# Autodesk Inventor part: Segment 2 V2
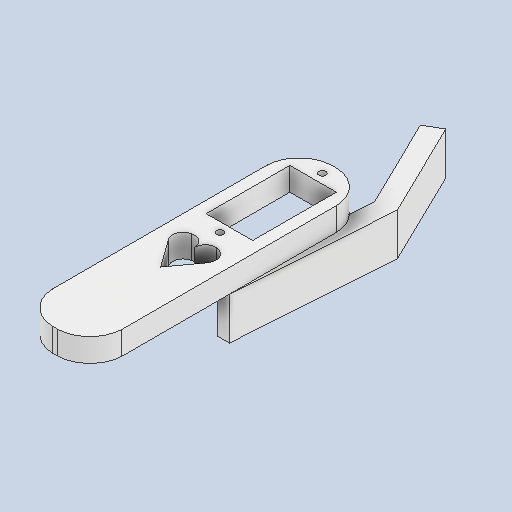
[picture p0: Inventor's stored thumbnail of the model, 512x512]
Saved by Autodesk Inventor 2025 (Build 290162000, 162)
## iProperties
Created: 2024-11
Part Number: Segment 2 V2
Material: ABS Plastic
Document SubType Name: Modeling
Designer: Braidyn
Density: 1.06 g/cm^3
Appearance: Smooth - White
Author: Braidyn
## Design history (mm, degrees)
sketch "Sketch1"
  geometry: L1 (9.525, 38.1)-(-9.525, 38.1); L2 (-9.525, 38.1)-(-9.525, -38.1); L3 (-9.525, -38.1)-(9.525, -38.1); L4 (9.525, -38.1)-(9.525, 38.1); L5 (9.525, 38.1)-(-9.525, -38.1); L6 (-9.525, 38.1)-(9.525, -38.1); L7 (9.525, -38.1)-(9.525, -28.575); L8 (9.525, -28.575)-(-9.525, -28.575); L9 (9.525, 38.1)-(9.525, 28.575); L10 (9.525, 28.575)-(-9.525, 28.575); A1 r 9.144 centre (0.389, 28.964) between (9.525, 28.575) and (0, 38.1); A2 r 9.144 centre (-0.389, 28.964) between (0, 38.1) and (-9.525, 28.575); A3 r 9.144 centre (0.389, -28.964) between (0, -38.1) and (9.525, -28.575); A4 r 9.144 centre (-0.389, -28.964) between (-9.525, -28.575) and (0, -38.1); 9 further points
  constraints: 20 end point, 8 point on circle, 4 centre point, 4 midpoint, 4 point on line, 3 perpendicular, 2 parallel, 1 horizontal
  dimensions: "d0" = 19.05 distance of L3.end L2.end; "d1" = 76.2 distance of L2.end L1.end; "d2" = 9.525 distance of L3.end L7.end; "d3" = 9.525 distance of L1.start L9.end; "d4" = 9.144 radius of A1; "d5" = 9.144 radius of A2; "d6" = 9.144 radius of A3; "d7" = 9.144 radius of A4
extrude "Extrusion1" new body sketch "Sketch1" distance "d8" = 6.35; taper "d9" = 0 deg
sketch "Sketch2"
  geometry: L1 (0, -38.1)-(0, -17.78); L2 (0.779, 38.1)-(-0.779, 38.1) reference; L3 (0, 38.1)-(0, 34.925); L4 (0, 34.925)-(0, 32.385); L5 (0, 32.385)-(0, 9.525); L6 (0, 9.525)-(0, 6.985); L7 (-6.35, 9.525)-(6.35, 9.525); L8 (6.35, 9.525)-(6.35, 32.385); L9 (6.35, 32.385)-(-6.35, 32.385); L10 (-6.35, 32.385)-(-6.35, 9.525); L11 (-6.35, 9.525)-(6.35, 32.385); L12 (6.35, 9.525)-(-6.35, 32.385); C1 r 0.952 at (0, 34.925); C2 r 0.953 at (0, 6.985); 2 further points
  constraints: 22 end point, 4 midpoint, 3 vertical, 2 centre point, 2 coincident, 2 parallel, 2 point on line, 1 horizontal, 1 perpendicular
  dimensions: "d10" = 20.32 distance of L1.start L1.end; "d11" = 3.175 distance of L3.start L3.end; "d12" = 1.905 diameter of C1; "d13" = 2.54 distance of L4.start L4.end; "d14" = 22.86 distance of L4.end L5.end; "d15" = 2.54 distance of L5.end L6.end; "d16" = 1.905 diameter of C2; "d17" = 12.7 distance of L9.end L8.end
extrude "Extrusion2" cut sketch "Sketch2" distance "d18" = 6.35; taper "d19" = 0 deg
sketch "Sketch3"
  geometry: L1 (-0.779, -38.1)-(0.779, -38.1) reference; L2 (0, -38.1)-(0, -17.78); L3 (5.557, -1.786)-(0.052, -9.319); L4 (0.052, -9.319)-(-5.572, -1.477); A1 r 2.839 centre (-3.15, 0.004) between (-3.549, 2.815) and (-5.572, -1.477); A2 r 2.891 centre (-2.891, 0) between (0, 0) and (-3.549, 2.815); A3 r 2.906 centre (2.906, -0.011) between (2.966, 2.894) and (0, 0); A4 r 3.052 centre (2.975, -0.159) between (5.557, -1.786) and (2.966, 2.894); 1 further point
  constraints: 8 point on circle, 6 end point, 4 centre point, 1 midpoint, 1 vertical
  dimensions: "d20" = 20.32 distance of L2.start L2.end
extrude "Extrusion3" cut sketch "Sketch3" distance "d21" = 6.35; taper "d22" = 0 deg
sketch "Sketch4"
  geometry: L1 (9.525, 29.354)-(9.525, -29.354) reference; L2 (9.525, 0)-(12.554, -42.849); L3 (12.554, -42.849)-(0, -68.638); L4 (0, -68.638)-(-4.399, -66.098); L5 (0, -68.638)-(5.08, -68.638); L6 (-4.399, -66.098)-(7.445, -41.766); L7 (7.445, -41.766)-(6.35, -25.028); L8 (6.35, -9.525)-(6.35, -32.385) reference; L9 (6.35, -25.028)-(6.35, 0); L10 (6.35, 0)-(9.525, 0); L11 (7.445, -41.766)-(-6.897, -41.766); L12 (0, -9.525)-(0, -32.385); L13 (-6.35, -32.385)-(6.35, -32.385) reference; 2 further points
  constraints: 20 end point, 2 horizontal, 2 midpoint, 2 point on line, 1 equal length, 1 parallel, 1 perpendicular
  dimensions: "d23" = 150 deg angle of L2 L3; "d24" = 5.08 distance of L3.end L4.end; "d25" = 150 deg angle of L5 L4
extrude "Extrusion4" join sketch "Sketch4" distance "d26" = 11.557; taper "d27" = 0 deg
body "Solid1"
